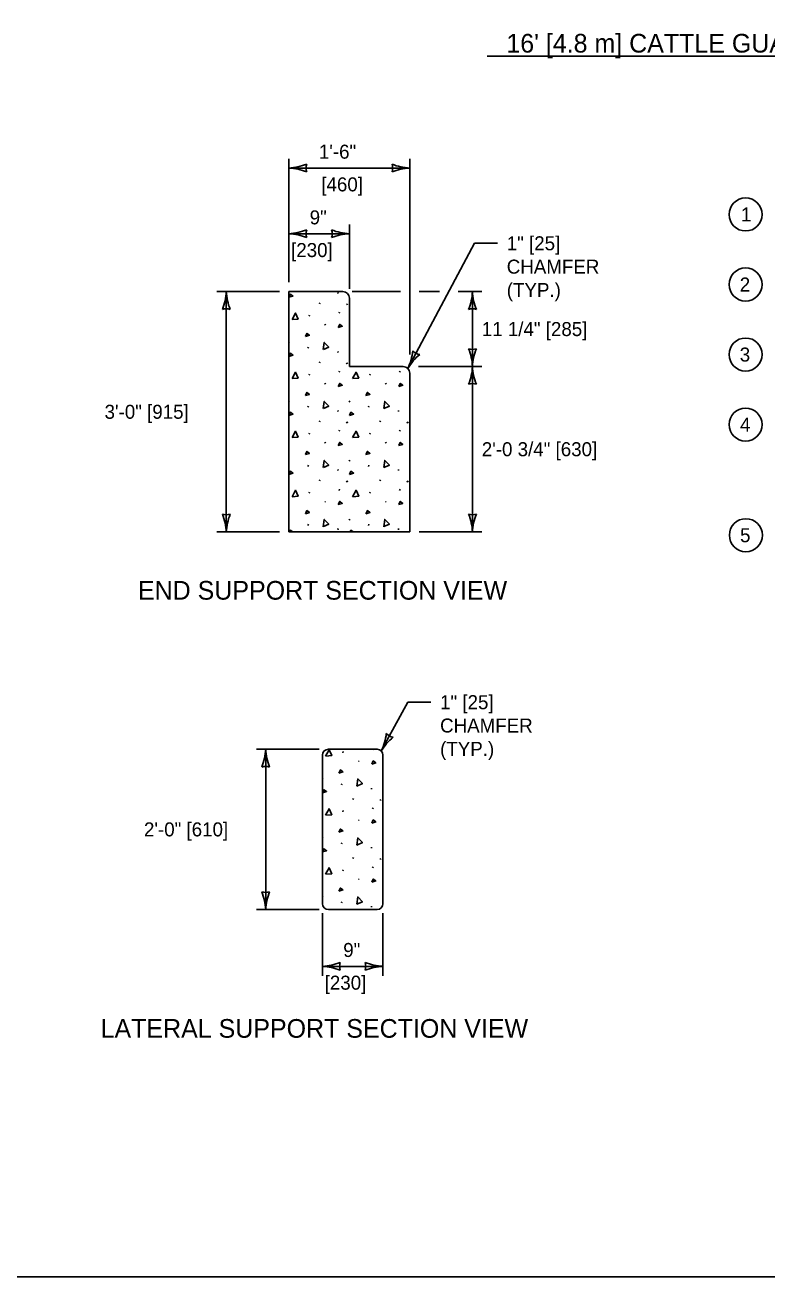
# Model space of a CAD drawing. Extents: x 49991.4 to 50021, y 49987.6 to 50011.4.
# Drawn here: x 50009.43 to 50012.61, y 49987.8 to 49993.16 of the extents above; entities that cross this region are included whole.
import ezdxf

# ---------------------------------------------------------------- set-up
doc = ezdxf.new("R2010")
doc.units = 0
for name, color, linetype in [('Level 1', 7, 'Continuous'), ('Level 2', 7, 'Continuous'), ('Level 3', 7, 'Continuous')]:
    doc.layers.add(name, color=color, linetype=linetype)

msp = doc.modelspace()

# ---------------------------------------------------------------- linework, layer by layer
at = {"layer": 'Level 1'}
for p, q in [((50010.7886, 49992.0193), (50010.558, 49992.0193)), ((50010.558, 49992.0193), (50010.558, 49990.9899)), ((50010.7678, 49992.016), (50010.7684, 49992.0111)), ((50010.6884, 49991.9668), (50010.6905, 49991.9716)), ((50010.8048, 49991.9668), (50010.8069, 49991.9635)), ((50010.8069, 49991.9655), (50010.8091, 49991.9623)), ((50010.8168, 49991.6986), (50010.8168, 49991.9912)), ((50010.6445, 49991.9142), (50010.6467, 49991.9191)), ((50010.7728, 49991.9266), (50010.775, 49991.9315)), ((50010.7122, 49991.8795), (50010.7144, 49991.8763)), ((50010.558, 49991.8015), (50010.559, 49991.8037)), ((50010.8161, 49991.7989), (50010.8168, 49991.8003)), ((50010.6391, 49991.7767), (50010.6413, 49991.7816)), ((50010.7678, 49991.7631), (50010.7684, 49991.7582)), ((50010.6884, 49991.7139), (50010.6905, 49991.7188)), ((50010.8048, 49991.7139), (50010.8069, 49991.7106)), ((50010.8069, 49991.7127), (50010.8091, 49991.7094)), ((50011.0474, 49991.6986), (50010.8168, 49991.6986)), ((50010.6445, 49991.6613), (50010.6467, 49991.6662)), ((50010.7728, 49991.6738), (50010.775, 49991.6786)), ((50010.9038, 49991.6613), (50010.906, 49991.6662)), ((50011.0321, 49991.6738), (50011.0343, 49991.6786)), ((50011.0755, 49990.9899), (50011.0755, 49991.6705)), ((50010.7122, 49991.6267), (50010.7144, 49991.6234)), ((50010.9715, 49991.6267), (50010.9737, 49991.6234)), ((50010.558, 49991.5487), (50010.559, 49991.5509)), ((50010.6391, 49991.5238), (50010.6413, 49991.5287)), ((50010.8161, 49991.546), (50010.8183, 49991.5509)), ((50010.8984, 49991.5238), (50010.9006, 49991.5287)), ((50011.0755, 49991.546), (50011.0755, 49991.5462)), ((50010.7678, 49991.5102), (50010.7684, 49991.5053)), ((50011.0271, 49991.5102), (50011.0277, 49991.5053)), ((50010.6884, 49991.461), (50010.6905, 49991.4659)), ((50010.7728, 49991.4209), (50010.775, 49991.4258)), ((50010.8048, 49991.461), (50010.8069, 49991.4578)), ((50010.8069, 49991.4598), (50010.8091, 49991.4565)), ((50010.9477, 49991.461), (50010.9499, 49991.4659)), ((50011.0321, 49991.4209), (50011.0343, 49991.4258)), ((50011.0641, 49991.461), (50011.0662, 49991.4578)), ((50011.0662, 49991.4598), (50011.0684, 49991.4565)), ((50010.6445, 49991.4084), (50010.6467, 49991.4133)), ((50010.7122, 49991.3738), (50010.7144, 49991.3705)), ((50010.9038, 49991.4084), (50010.906, 49991.4133)), ((50010.9715, 49991.3738), (50010.9737, 49991.3705)), ((50010.558, 49991.2958), (50010.559, 49991.298)), ((50010.6391, 49991.2709), (50010.6413, 49991.2758)), ((50010.8161, 49991.2931), (50010.8183, 49991.298)), ((50010.8984, 49991.2709), (50010.9006, 49991.2758)), ((50011.0755, 49991.2931), (50011.0755, 49991.2933)), ((50010.6884, 49991.2082), (50010.6905, 49991.213)), ((50010.7678, 49991.2573), (50010.7684, 49991.2525)), ((50010.8048, 49991.2082), (50010.8069, 49991.2049)), ((50010.8069, 49991.2069), (50010.8091, 49991.2037)), ((50010.9477, 49991.2082), (50010.9499, 49991.213)), ((50011.0271, 49991.2573), (50011.0277, 49991.2525)), ((50011.0641, 49991.2082), (50011.0662, 49991.2049)), ((50011.0662, 49991.2069), (50011.0684, 49991.2037)), ((50010.6445, 49991.1556), (50010.6467, 49991.1604)), ((50010.7728, 49991.168), (50010.775, 49991.1729)), ((50010.9038, 49991.1556), (50010.906, 49991.1604)), ((50011.0321, 49991.168), (50011.0343, 49991.1729)), ((50010.7122, 49991.1209), (50010.7144, 49991.1177)), ((50010.9715, 49991.1209), (50010.9737, 49991.1177)), ((50010.558, 49991.0429), (50010.559, 49991.0451)), ((50010.8161, 49991.0403), (50010.8183, 49991.0451)), ((50010.558, 49990.9899), (50011.0755, 49990.9899)), ((50010.6391, 49991.0181), (50010.6413, 49991.0229)), ((50010.7678, 49991.0045), (50010.7684, 49990.9996)), ((50010.8984, 49991.0181), (50010.9006, 49991.0229)), ((50011.0271, 49991.0045), (50011.0277, 49990.9996)), ((50011.0755, 49991.0403), (50011.0755, 49991.0404)), ((50010.7018, 49990.034), (50010.7018, 49989.3977)), ((50010.9356, 49990.059), (50010.7268, 49990.059)), ((50010.7882, 49990.0442), (50010.7904, 49990.0491)), ((50010.9165, 49990.0567), (50010.9176, 49990.059)), ((50010.9606, 49989.3977), (50010.9606, 49990.034)), ((50010.8559, 49990.0096), (50010.8581, 49990.0063)), ((50010.7018, 49989.9317), (50010.7027, 49989.9338)), ((50010.9598, 49989.9289), (50010.9606, 49989.9305)), ((50010.7828, 49989.9067), (50010.785, 49989.9116)), ((50010.9115, 49989.8931), (50010.9121, 49989.8882)), ((50010.8321, 49989.8439), (50010.8342, 49989.8488)), ((50010.9485, 49989.8439), (50010.9506, 49989.8407)), ((50010.9506, 49989.8427), (50010.9528, 49989.8394)), ((50010.7882, 49989.7913), (50010.7904, 49989.7962)), ((50010.8559, 49989.7567), (50010.8581, 49989.7534)), ((50010.9165, 49989.8038), (50010.9187, 49989.8087)), ((50010.7018, 49989.6789), (50010.7027, 49989.6809)), ((50010.7828, 49989.6538), (50010.785, 49989.6587)), ((50010.9598, 49989.676), (50010.9606, 49989.6776)), ((50010.8321, 49989.5911), (50010.8342, 49989.5959)), ((50010.9115, 49989.6402), (50010.9121, 49989.6354)), ((50010.7882, 49989.5385), (50010.7904, 49989.5433)), ((50010.9165, 49989.5509), (50010.9187, 49989.5558)), ((50010.9485, 49989.5911), (50010.9506, 49989.5878)), ((50010.9506, 49989.5898), (50010.9528, 49989.5866)), ((50010.8559, 49989.5038), (50010.8581, 49989.5006)), ((50010.7018, 49989.426), (50010.7027, 49989.428)), ((50010.7828, 49989.401), (50010.785, 49989.4058)), ((50010.9115, 49989.3874), (50010.9121, 49989.3825)), ((50010.9598, 49989.4232), (50010.9606, 49989.4248)), ((50010.7268, 49989.3727), (50010.9356, 49989.3727))]:
    msp.add_line(p, q, dxfattribs=at)
msp.add_lwpolyline([(49999.3835, 49998.9992), (50016.7501, 49998.9992), (50016.7501, 49987.7988), (49999.3835, 49987.7988)], close=True, dxfattribs=at)
for points in [[(50010.558, 49991.9951), (50010.5644, 49992.0084), (50010.5752, 49992.0003), (50010.558, 49991.9949)], [(50010.5715, 49991.8996), (50010.5861, 49991.9272), (50010.5974, 49991.9017), (50010.572, 49991.8996)], [(50010.769, 49991.8655), (50010.7755, 49991.879), (50010.7864, 49991.8709), (50010.769, 49991.8655)], [(50010.6284, 49991.8268), (50010.6349, 49991.8403), (50010.6457, 49991.8322), (50010.6284, 49991.8268)], [(50010.705, 49991.7711), (50010.7093, 49991.802), (50010.7287, 49991.782), (50010.7055, 49991.7713)], [(50010.558, 49991.7422), (50010.5644, 49991.7556), (50010.5752, 49991.7475), (50010.558, 49991.7421)], [(50010.5715, 49991.6467), (50010.5861, 49991.6743), (50010.5974, 49991.6489), (50010.572, 49991.6467)], [(50010.8308, 49991.6467), (50010.8454, 49991.6743), (50010.8567, 49991.6489), (50010.8313, 49991.6467)], [(50010.6284, 49991.5739), (50010.6349, 49991.5874), (50010.6457, 49991.5793), (50010.6284, 49991.5739)], [(50010.769, 49991.6126), (50010.7755, 49991.6261), (50010.7864, 49991.618), (50010.769, 49991.6126)], [(50010.8877, 49991.5739), (50010.8942, 49991.5874), (50010.905, 49991.5793), (50010.8877, 49991.5739)], [(50011.0284, 49991.6126), (50011.0348, 49991.6261), (50011.0457, 49991.618), (50011.0284, 49991.6126)], [(50010.705, 49991.5182), (50010.7093, 49991.5492), (50010.7287, 49991.5291), (50010.7055, 49991.5184)], [(50010.9643, 49991.5182), (50010.9686, 49991.5492), (50010.988, 49991.5291), (50010.9648, 49991.5184)], [(50010.558, 49991.4894), (50010.5644, 49991.5027), (50010.5752, 49991.4946), (50010.558, 49991.4892)], [(50010.8172, 49991.4892), (50010.8237, 49991.5027), (50010.8346, 49991.4946), (50010.8172, 49991.4892)], [(50010.5715, 49991.3938), (50010.5861, 49991.4214), (50010.5974, 49991.396), (50010.572, 49991.3938)], [(50010.8308, 49991.3938), (50010.8454, 49991.4214), (50010.8567, 49991.396), (50010.8313, 49991.3938)], [(50010.769, 49991.3597), (50010.7755, 49991.3733), (50010.7864, 49991.3651), (50010.769, 49991.3597)], [(50011.0284, 49991.3597), (50011.0348, 49991.3733), (50011.0457, 49991.3651), (50011.0284, 49991.3597)], [(50010.6284, 49991.321), (50010.6349, 49991.3346), (50010.6457, 49991.3264), (50010.6284, 49991.321)], [(50010.8877, 49991.321), (50010.8942, 49991.3346), (50010.905, 49991.3264), (50010.8877, 49991.321)], [(50010.705, 49991.2653), (50010.7093, 49991.2963), (50010.7287, 49991.2763), (50010.7055, 49991.2655)], [(50010.9643, 49991.2653), (50010.9686, 49991.2963), (50010.988, 49991.2763), (50010.9648, 49991.2655)], [(50010.558, 49991.2365), (50010.5644, 49991.2498), (50010.5752, 49991.2417), (50010.558, 49991.2363)], [(50010.8172, 49991.2363), (50010.8237, 49991.2498), (50010.8346, 49991.2417), (50010.8172, 49991.2363)], [(50010.5715, 49991.141), (50010.5861, 49991.1686), (50010.5974, 49991.1431), (50010.572, 49991.141)], [(50010.8308, 49991.141), (50010.8454, 49991.1686), (50010.8567, 49991.1431), (50010.8313, 49991.141)], [(50010.769, 49991.1069), (50010.7755, 49991.1204), (50010.7864, 49991.1123), (50010.769, 49991.1069)], [(50011.0284, 49991.1069), (50011.0348, 49991.1204), (50011.0457, 49991.1123), (50011.0284, 49991.1069)], [(50010.6284, 49991.0682), (50010.6349, 49991.0817), (50010.6457, 49991.0736), (50010.6284, 49991.0682)], [(50010.8877, 49991.0682), (50010.8942, 49991.0817), (50010.905, 49991.0736), (50010.8877, 49991.0682)], [(50010.561, 49990.9899), (50010.5644, 49990.997), (50010.5739, 49990.9899)], [(50010.705, 49991.0125), (50010.7093, 49991.0434), (50010.7287, 49991.0234), (50010.7055, 49991.0127)], [(50010.8203, 49990.9899), (50010.8237, 49990.997), (50010.8332, 49990.9899)], [(50010.9643, 49991.0125), (50010.9686, 49991.0434), (50010.988, 49991.0234), (50010.9648, 49991.0127)], [(50010.7152, 49990.0296), (50010.7298, 49990.0572), (50010.7411, 49990.0318), (50010.7157, 49990.0296)], [(50010.9127, 49989.9955), (50010.9192, 49990.009), (50010.9301, 49990.0009), (50010.9127, 49989.9955)], [(50010.7721, 49989.9568), (50010.7786, 49989.9703), (50010.7894, 49989.9622), (50010.7721, 49989.9568)], [(50010.8487, 49989.9011), (50010.853, 49989.9321), (50010.8724, 49989.912), (50010.8492, 49989.9013)], [(50010.7018, 49989.8724), (50010.7081, 49989.8856), (50010.7189, 49989.8775), (50010.7018, 49989.8721)], [(50010.7152, 49989.7767), (50010.7298, 49989.8043), (50010.7411, 49989.7789), (50010.7157, 49989.7767)], [(50010.7721, 49989.7039), (50010.7786, 49989.7175), (50010.7894, 49989.7093), (50010.7721, 49989.7039)], [(50010.9127, 49989.7426), (50010.9192, 49989.7562), (50010.9301, 49989.748), (50010.9127, 49989.7426)], [(50010.8487, 49989.6482), (50010.853, 49989.6792), (50010.8724, 49989.6592), (50010.8492, 49989.6484)], [(50010.7018, 49989.6196), (50010.7081, 49989.6327), (50010.7189, 49989.6246), (50010.7018, 49989.6193)], [(50010.7152, 49989.5239), (50010.7298, 49989.5515), (50010.7411, 49989.526), (50010.7157, 49989.5239)], [(50010.9127, 49989.4898), (50010.9192, 49989.5033), (50010.9301, 49989.4952), (50010.9127, 49989.4898)], [(50010.7721, 49989.4511), (50010.7786, 49989.4646), (50010.7894, 49989.4565), (50010.7721, 49989.4511)], [(50010.8487, 49989.3954), (50010.853, 49989.4263), (50010.8724, 49989.4063), (50010.8492, 49989.3956)]]:
    msp.add_lwpolyline(points, dxfattribs=at)
for centre, radius, start, end in [((50010.7886, 49991.9912), 0.0281, 0.0336, 90), ((50011.0474, 49991.6705), 0.0281, 0, 90), ((50010.7268, 49990.034), 0.025, 90.0082, 180), ((50010.9356, 49990.034), 0.025, 0, 90), ((50010.7268, 49989.3977), 0.025, 180, 270), ((50010.9356, 49989.3977), 0.025, 270, 360)]:
    msp.add_arc(centre, radius, start, end, dxfattribs=at)
at = {"layer": 'Level 2'}
msp.add_line((50011.407, 49993.0272), (50013.0786, 49993.0272), dxfattribs=at)
for centre in [(50012.5138, 49992.3498), (50012.5138, 49992.0498), (50012.5138, 49991.7498), (50012.5138, 49991.4498), (50012.5148, 49990.976)]:
    msp.add_circle(centre, 0.0707, dxfattribs=at)
at = {"layer": 'Level 3'}
for p, q in [((50010.558, 49992.0593), (50010.558, 49992.5887)), ((50010.558, 49992.5487), (50011.0755, 49992.5487)), ((50011.0755, 49991.7502), (50011.0755, 49992.5887)), ((50010.8168, 49992.0312), (50010.8168, 49992.3073)), ((50010.558, 49992.2673), (50010.8168, 49992.2673)), ((50011.0673, 49991.6904), (50011.3532, 49992.2263)), ((50011.3532, 49992.2263), (50011.4508, 49992.2263)), ((50010.518, 49992.0193), (50010.2496, 49992.0193)), ((50010.2896, 49992.0193), (50010.2896, 49990.9899)), ((50010.8286, 49992.0193), (50011.0355, 49992.0193)), ((50011.1155, 49992.0193), (50011.2027, 49992.0193)), ((50011.2827, 49992.0193), (50011.3839, 49992.0193)), ((50011.3439, 49992.0193), (50011.3439, 49991.6986)), ((50011.1124, 49991.6986), (50011.3839, 49991.6986)), ((50011.3439, 49991.6986), (50011.3439, 49990.9899)), ((50010.518, 49990.9899), (50010.2496, 49990.9899)), ((50011.1155, 49990.9899), (50011.3839, 49990.9899)), ((50010.9532, 49990.0517), (50011.0677, 49990.2608)), ((50011.0677, 49990.2608), (50011.1653, 49990.2608)), ((50010.6868, 49990.059), (50010.4184, 49990.059)), ((50010.4584, 49990.059), (50010.4584, 49989.3727)), ((50010.6868, 49989.3727), (50010.4184, 49989.3727)), ((50010.7018, 49989.3577), (50010.7018, 49989.0893)), ((50010.9606, 49989.3577), (50010.9606, 49989.0893)), ((50010.9606, 49989.1293), (50010.7018, 49989.1293))]:
    msp.add_line(p, q, dxfattribs=at)
for centre, radius, start, end in [((50010.5465, 49992.7814), 0.233, 272.8273, 292.0772), ((50010.5489, 49992.3266), 0.2223, 67.456, 87.6395), ((50010.6862, 49992.5487), 0.0548, 162.1388, 197.8612), ((50011.0847, 49992.7708), 0.2223, 247.456, 267.6395), ((50010.9473, 49992.5487), 0.0548, 342.1388, 17.8612), ((50011.087, 49992.316), 0.233, 92.8273, 112.0772), ((50010.5465, 49992.5001), 0.233, 272.8273, 292.0772), ((50010.6862, 49992.2673), 0.0548, 162.1388, 197.8612), ((50010.8259, 49992.4895), 0.2223, 247.456, 267.6395), ((50010.6886, 49992.2673), 0.0548, 342.1388, 17.8612), ((50010.5489, 49992.0452), 0.2223, 67.456, 87.6395), ((50010.8283, 49992.0346), 0.233, 92.8273, 112.0772), ((50010.0675, 49992.0284), 0.2223, 337.456, 357.6395), ((50010.5223, 49992.0308), 0.233, 182.8273, 202.0772), ((50011.1218, 49992.0284), 0.2223, 337.456, 357.6395), ((50011.5766, 49992.0308), 0.233, 182.8273, 202.0772), ((50010.2896, 49991.8911), 0.0548, 72.1388, 107.8612), ((50011.3439, 49991.8911), 0.0548, 72.1388, 107.8612), ((50010.8566, 49991.7898), 0.233, 334.7473, 353.9972), ((50011.259, 49991.5778), 0.2223, 129.376, 149.5595), ((50011.1276, 49991.8035), 0.0548, 224.0588, 259.7812), ((50011.3439, 49991.8269), 0.0548, 252.1388, 287.8612), ((50011.1112, 49991.6872), 0.233, 2.8273, 22.0772), ((50011.5661, 49991.6895), 0.2223, 157.456, 177.6395), ((50011.1218, 49991.7078), 0.2223, 337.456, 357.6395), ((50011.5766, 49991.7101), 0.233, 182.8273, 202.0772), ((50011.3439, 49991.5704), 0.0548, 72.1388, 107.8612), ((50010.2896, 49991.1181), 0.0548, 252.1388, 287.8612), ((50010.0569, 49990.9784), 0.233, 2.8273, 22.0772), ((50010.5118, 49990.9807), 0.2223, 157.456, 177.6395), ((50011.3439, 49991.1181), 0.0548, 252.1388, 287.8612), ((50011.1112, 49990.9784), 0.233, 2.8273, 22.0772), ((50011.5661, 49990.9807), 0.2223, 157.456, 177.6395), ((50010.7436, 49990.1534), 0.233, 334.1261, 353.3759), ((50011.1437, 49989.937), 0.2223, 128.7548, 148.9383), ((50011.0148, 49990.1641), 0.0548, 223.4376, 259.1599), ((50010.2363, 49990.0682), 0.2223, 337.456, 357.6395), ((50010.6911, 49990.0705), 0.233, 182.8273, 202.0772), ((50010.4584, 49989.9308), 0.0548, 72.1388, 107.8612), ((50010.4584, 49989.5009), 0.0548, 252.1388, 287.8612), ((50010.2257, 49989.3612), 0.233, 2.8273, 22.0772), ((50010.6805, 49989.3636), 0.2223, 157.456, 177.6395), ((50010.6903, 49989.362), 0.233, 272.8273, 292.0772), ((50010.6926, 49988.9072), 0.2223, 67.456, 87.6395), ((50010.83, 49989.1293), 0.0548, 162.1388, 197.8612), ((50010.9697, 49989.3515), 0.2223, 247.456, 267.6395), ((50010.8323, 49989.1293), 0.0548, 342.1388, 17.8612), ((50010.972, 49988.8966), 0.233, 92.8273, 112.0772)]:
    msp.add_arc(centre, radius, start, end, dxfattribs=at)

# ---------------------------------------------------------------- texts
at = {"layer": 'Level 2'}
for s, height, p in [("16' [4.8 m] CATTLE GUARD END SUPPORT  DETAIL", 0.08, (50011.4892, 49993.0432)), ('1\'-6"', 0.06, (50010.6861, 49992.5887)), ('[460]', 0.06, (50010.6966, 49992.4487)), ('9"', 0.06, (50010.6468, 49992.3073)), ('1', 0.06, (50012.494, 49992.3198)), ('[230]', 0.06, (50010.5672, 49992.1673)), ('1" [25] ', 0.06, (50011.4908, 49992.1963)), ('CHAMFER', 0.06, (50011.4908, 49992.0963)), ('2', 0.06, (50012.4886, 49992.0198)), ('(TYP.)', 0.06, (50011.4908, 49991.9963)), ('11 1/4" [285]', 0.06, (50011.3839, 49991.829)), ('3', 0.06, (50012.4886, 49991.7198)), ('3\'-0" [915]', 0.06, (50009.7684, 49991.4746)), ('4', 0.06, (50012.4898, 49991.4198)), ('2\'-0 3/4" [630]', 0.06, (50011.3839, 49991.3143)), ('5', 0.06, (50012.4899, 49990.946)), ('END SUPPORT SECTION VIEW', 0.08, (50009.9114, 49990.6999)), ('1" [25] ', 0.06, (50011.2053, 49990.2308)), ('CHAMFER', 0.06, (50011.2053, 49990.1308)), ('(TYP.)', 0.06, (50011.2053, 49990.0308)), ('2\'-0" [610]', 0.06, (50009.9372, 49989.6859)), ('9"', 0.06, (50010.7905, 49989.1693)), ('[230]', 0.06, (50010.711, 49989.0293)), ('LATERAL SUPPORT SECTION VIEW', 0.08, (50009.7514, 49988.8234))]:
    msp.add_text(s, height=height, dxfattribs=at).set_placement(p)

doc.saveas('drawing.dxf')
